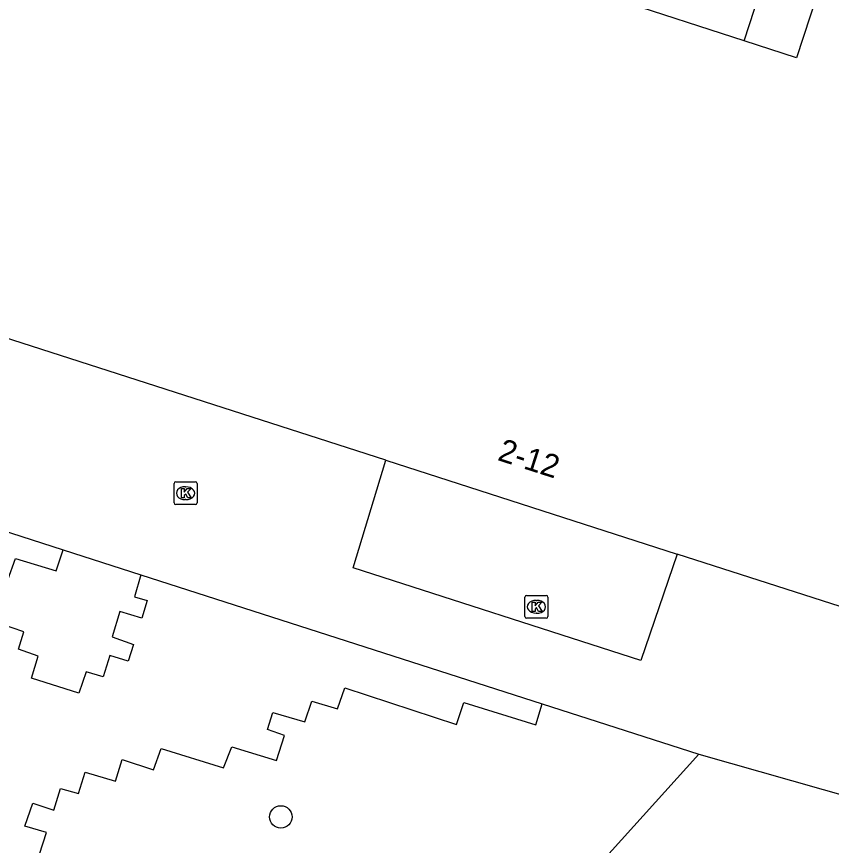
# Model space of a CAD drawing. Extents: x 160676 to 161153, y 383244 to 383713.
# Drawn here: x 161027.96 to 161063.54, y 383297.79 to 383334 of the extents above; entities that cross this region are included whole.
import ezdxf

# ---------------------------------------------------------------- set-up
doc = ezdxf.new("R2010")
doc.units = 0
for name, color, linetype in [('IMGEO_Boom', 7, 'Continuous'), ('IMGEO_Kolk', 7, 'Continuous'), ('IMGEO_Pand', 7, 'Continuous'), ('IMGEO_Pand_nummerreeks', 7, 'Continuous'), ('IMGEO_Voetpad_open', 7, 'Continuous')]:
    doc.layers.add(name, color=color, linetype=linetype)

msp = doc.modelspace()

# ---------------------------------------------------------------- linework, layer by layer
at = {"layer": 'IMGEO_Boom'}
msp.add_circle((161039.499, 383299.033), 0.489, dxfattribs=at)
at = {"layer": 'IMGEO_Kolk'}
for p, q in [((161034.837, 383312.75), (161034.837, 383313.602)), ((161034.912, 383313.676), (161035.764, 383313.676)), ((161035.838, 383313.602), (161035.838, 383312.75)), ((161035.325, 383313.456), (161035.35, 383313.456)), ((161035.348, 383312.896), (161035.323, 383312.896)), ((161035.764, 383312.676), (161034.912, 383312.676)), ((161050.158, 383307.786), (161050.158, 383308.638)), ((161050.233, 383308.712), (161051.085, 383308.712)), ((161050.646, 383308.492), (161050.671, 383308.492)), ((161051.159, 383308.638), (161051.159, 383307.786)), ((161050.669, 383307.932), (161050.644, 383307.932)), ((161051.085, 383307.712), (161050.233, 383307.712))]:
    msp.add_line(p, q, dxfattribs=at)
for points in [[(161034.837, 383312.75), (161034.837, 383313.602)], [(161034.912, 383313.676), (161035.764, 383313.676)], [(161035.838, 383313.602), (161035.838, 383312.75)], [(161035.158, 383313.376), (161035.281, 383313.376), (161035.281, 383313.225), (161035.411, 383313.376), (161035.575, 383313.376), (161035.429, 383313.225), (161035.582, 383312.976), (161035.43, 383312.976), (161035.345, 383313.14), (161035.281, 383313.073), (161035.281, 383312.976), (161035.158, 383312.976), (161035.158, 383313.376)], [(161035.764, 383312.676), (161034.912, 383312.676)], [(161050.158, 383307.786), (161050.158, 383308.638)], [(161050.233, 383308.712), (161051.085, 383308.712)], [(161051.159, 383308.638), (161051.159, 383307.786)], [(161050.479, 383308.412), (161050.602, 383308.412), (161050.602, 383308.261), (161050.732, 383308.412), (161050.896, 383308.412), (161050.75, 383308.261), (161050.903, 383308.012), (161050.751, 383308.012), (161050.666, 383308.176), (161050.602, 383308.109), (161050.602, 383308.012), (161050.479, 383308.012), (161050.479, 383308.412)], [(161051.085, 383307.712), (161050.233, 383307.712)]]:
    msp.add_lwpolyline(points, dxfattribs=at)
for centre, start, end in [((161034.914, 383313.6), 91.552, 178.448), ((161034.914, 383313.6), 91.552, 178.448), ((161035.762, 383313.6), 1.552, 88.448), ((161035.762, 383313.6), 1.552, 88.448), ((161034.914, 383312.752), 181.552, 268.448), ((161034.914, 383312.752), 181.552, 268.448), ((161035.762, 383312.752), 271.552, 358.448), ((161035.762, 383312.752), 271.552, 358.448), ((161050.235, 383308.636), 91.552, 178.448), ((161050.235, 383308.636), 91.552, 178.448), ((161051.083, 383308.636), 1.552, 88.448), ((161051.083, 383308.636), 1.552, 88.448), ((161050.235, 383307.788), 181.552, 268.448), ((161050.235, 383307.788), 181.552, 268.448), ((161051.083, 383307.788), 271.552, 358.448), ((161051.083, 383307.788), 271.552, 358.448)]:
    msp.add_arc(centre, 0.0765, start, end, dxfattribs=at)
for centre, major_axis, ratio, start_param, end_param in [((161035.324, 383313.176), (-0.387, 0.002), 0.722429, 4.712389, 7.853982), ((161035.349, 383313.176), (-0.39, 0.002), 0.717154, 1.570796, 4.712389), ((161050.645, 383308.212), (-0.387, 0.002), 0.722429, 4.712389, 7.853982), ((161050.67, 383308.212), (-0.39, 0.002), 0.717154, 1.570796, 4.712389)]:
    msp.add_ellipse(centre, major_axis=major_axis, ratio=ratio, start_param=start_param, end_param=end_param, dxfattribs=at)
at = {"layer": 'IMGEO_Pand'}
for points in [[(161062.925, 383334.963), (161062.023, 383332.191), (161059.734, 383332.932)], [(161059.734, 383332.932), (161054.249, 383334.707)], [(161074.876, 383328.83), (161074.649, 383328.092), (161075.413, 383327.845), (161073.926, 383323.193), (161075.639, 383322.641), (161071.867, 383310.899), (161070.205, 383311.433), (161068.681, 383306.695), (161056.802, 383310.518)], [(161044.076, 383314.613), (161003.126, 383327.791), (161000, 383317.976), (160994.422, 383300.461)], [(161044.076, 383314.613), (161056.802, 383310.518)]]:
    msp.add_lwpolyline(points, dxfattribs=at)
at = {"layer": 'IMGEO_Voetpad_open'}
for points in [[(161059.734, 383332.932), (161060.636, 383335.716), (161062.925, 383334.963)], [(161056.802, 383310.518), (161055.215, 383305.86), (161042.651, 383309.908), (161044.076, 383314.613)], [(161020.455, 383313.768), (161029.994, 383310.701)], [(161033.388, 383309.609), (161033.111, 383308.651), (161033.666, 383308.484), (161033.431, 383307.723), (161032.471, 383308.012), (161032.129, 383306.903), (161033.061, 383306.57), (161032.831, 383305.832), (161032.024, 383306.08), (161031.735, 383305.158), (161030.992, 383305.374), (161030.672, 383304.434), (161028.611, 383305.098), (161028.907, 383306.061), (161028.038, 383306.357), (161028.281, 383307.126), (161027.262, 383307.47), (161027.588, 383308.632), (161026.684, 383308.883), (161026.889, 383309.648), (161027.583, 383309.39), (161027.916, 383310.325), (161029.691, 383309.783), (161029.994, 383310.701)], [(161029.994, 383310.701), (161033.388, 383309.609)], [(161033.388, 383309.609), (161050.91, 383303.976)], [(161028.964, 383297.406), (161029.264, 383298.355), (161028.312, 383298.632), (161028.662, 383299.636), (161029.584, 383299.33), (161029.877, 383300.269), (161030.659, 383300.053), (161030.954, 383300.992), (161032.278, 383300.589), (161032.563, 383301.537), (161033.932, 383301.096), (161034.277, 383302.021), (161037, 383301.174), (161037.358, 383302.095), (161039.31, 383301.493), (161039.655, 383302.597), (161038.919, 383302.854), (161039.154, 383303.596), (161040.543, 383303.185), (161040.846, 383304.095), (161041.978, 383303.75), (161042.298, 383304.675), (161047.165, 383303.078), (161047.486, 383304.035), (161050.64, 383303.056), (161050.91, 383303.976)], [(161050.91, 383303.976), (161057.751, 383301.776)], [(161057.751, 383301.776), (161040.997, 383283.21)], [(161057.751, 383301.776), (161072.558, 383297.57), (161074.2, 383297.033)]]:
    msp.add_lwpolyline(points, dxfattribs=at)

# ---------------------------------------------------------------- texts
at = {"layer": 'IMGEO_Pand_nummerreeks'}
msp.add_text('2-12', height=1, rotation=342.1638, dxfattribs=at).set_placement((161048.918, 383314.631))

doc.saveas('drawing.dxf')
